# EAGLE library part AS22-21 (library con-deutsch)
DEUTSCH Connector
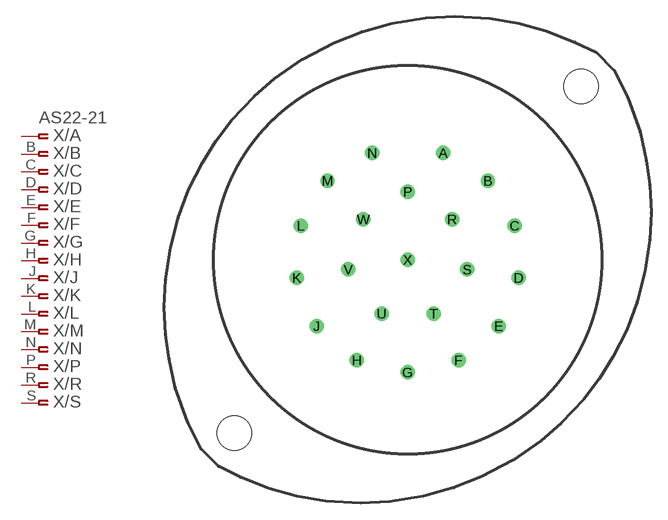
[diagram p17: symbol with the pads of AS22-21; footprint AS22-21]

Designator prefix X; gates /A=PINF_VAL /B=ASPINF /C=ASPINF /D=ASPINF /E=ASPINF /F=ASPINF /G=ASPINF /H=ASPINF /J=ASPINF /K=ASPINF /L=ASPINF /M=ASPINF /N=ASPINF /P=ASPINF /R=ASPINF /S=ASPINF /T=ASPINF /U=ASPINF /V=ASPINF /W=ASPINF /X=ASPINF

## AS22-21 (OC_FARNELL: unknown; OC_NEWARK: unknown)  [AS22-21]
A  /A:1  pas
B  /B:1  pas
C  /C:1  pas
D  /D:1  pas
E  /E:1  pas
F  /F:1  pas
G  /G:1  pas
H  /H:1  pas
J  /J:1  pas
K  /K:1  pas
L  /L:1  pas
M  /M:1  pas
N  /N:1  pas
P  /P:1  pas
R  /R:1  pas
S  /S:1  pas
T  /T:1  pas
U  /U:1  pas
V  /V:1  pas
W  /W:1  pas
X  /X:1  pas

## Footprint AS22-21 (pad centres in mm)
DEUTSCH Connector
drill 0.813 round: A 3.251,9.779; B 7.341,7.239; C 9.804,3.124; D 10.16,-1.651; E 8.331,-6.071; F 4.648,-9.195; G 0,-10.312; H -4.648,-9.195; J -8.331,-6.071; K -10.16,-1.651; L -9.804,3.124; M -7.341,7.239; N -3.251,9.779; P 0,6.223; R 4.064,3.708; S 5.436,-0.889; T 2.388,-4.928; U -2.388,-4.928; V -5.436,-0.889; W -4.064,3.708; X 0,0
hole 3.2 at -15.875,-15.875
hole 3.2 at 15.875,15.875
